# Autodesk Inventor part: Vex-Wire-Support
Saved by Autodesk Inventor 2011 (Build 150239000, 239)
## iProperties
Created: 2007-08
Part Number: Vex-Wire-Support
Document SubType Name: Modeling
Density: 1 g/cm^3
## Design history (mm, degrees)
feature "Base1"
body "Solid1"
